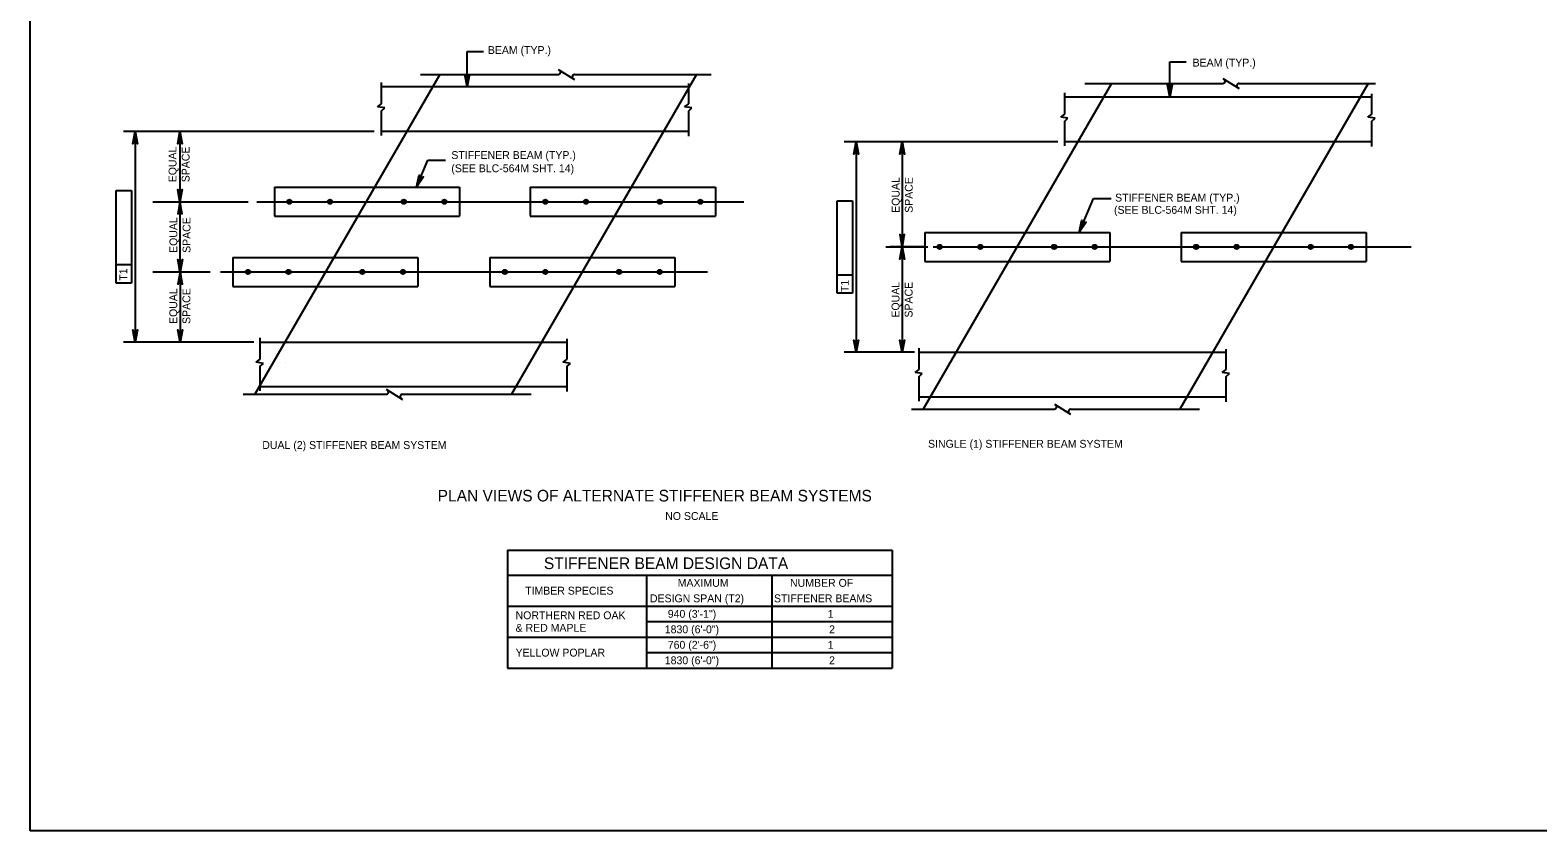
# Model space of a CAD drawing. Extents: x 638175 to 640495, y 294277 to 298435.
# Drawn here: x 639316 to 639891, y 296074 to 296380 of the extents above; entities that cross this region are included whole.
import ezdxf

# ---------------------------------------------------------------- set-up
doc = ezdxf.new("R2010")
doc.units = 0
for name, color, linetype in [('10', 7, 'Continuous'), ('2', 7, 'Continuous'), ('3', 7, 'Continuous'), ('4', 7, 'Continuous'), ('8', 7, 'Continuous')]:
    doc.layers.add(name, color=color, linetype=linetype)

msp = doc.modelspace()

# ---------------------------------------------------------------- linework, layer by layer
at = {"layer": '10'}
for p, q in [((639498.49, 296181.49), (639498.49, 296136.52)), ((639498.49, 296181.49), (639645.13, 296181.49)), ((639645.13, 296181.49), (639645.13, 296136.52)), ((639498.49, 296171.95), (639645.13, 296171.95)), ((639551.47, 296171.95), (639551.47, 296136.52)), ((639599.24, 296171.95), (639599.24, 296136.52)), ((639498.49, 296160.14), (639645.13, 296160.14)), ((639551.47, 296154.23), (639645.13, 296154.23)), ((639498.49, 296148.33), (639645.13, 296148.33)), ((639551.47, 296142.42), (639645.13, 296142.42)), ((639498.49, 296136.52), (639645.13, 296136.52))]:
    msp.add_line(p, q, dxfattribs=at)
at = {"layer": '2'}
for p, q in [((639316.46, 296074.46), (639316.46, 296638.46)), ((639472.63, 296362.87), (639402.14, 296240.92)), ((639570.46, 296362.87), (639499.97, 296240.92)), ((639728.68, 296359.46), (639656.9, 296235.27)), ((639826.52, 296359.46), (639754.73, 296235.27)), ((640102.46, 296074.46), (639316.46, 296074.46))]:
    msp.add_line(p, q, dxfattribs=at)
at = {"layer": '3'}
for p, q in [((639517.81, 296364.81), (639523.97, 296360.94)), ((639450.43, 296351.71), (639450.43, 296359.81)), ((639450.43, 296358.24), (639567.51, 296358.24)), ((639465.21, 296362.87), (639517.74, 296362.87)), ((639523.96, 296362.87), (639576.03, 296362.87)), ((639567.51, 296351.71), (639567.51, 296359.43)), ((639718.56, 296359.46), (639771.1, 296359.46)), ((639771.17, 296361.4), (639777.33, 296357.52)), ((639777.31, 296359.46), (639829.39, 296359.46)), ((639710.87, 296347.79), (639710.87, 296355.88)), ((639710.87, 296354.32), (639827.95, 296354.32)), ((639827.95, 296347.79), (639827.95, 296355.51)), ((639448.89, 296350.52), (639450.43, 296351.71)), ((639451.65, 296350.1), (639448.89, 296350.52)), ((639450.43, 296349), (639451.65, 296350.1)), ((639450.43, 296339.58), (639450.43, 296349)), ((639565.97, 296350.52), (639567.51, 296351.71)), ((639568.73, 296350.1), (639565.97, 296350.52)), ((639567.51, 296349), (639568.73, 296350.1)), ((639567.51, 296339.39), (639567.51, 296349)), ((639709.33, 296346.6), (639710.87, 296347.79)), ((639712.09, 296346.17), (639709.33, 296346.6)), ((639710.87, 296345.08), (639712.09, 296346.17)), ((639826.41, 296346.6), (639827.95, 296347.79)), ((639829.16, 296346.17), (639826.41, 296346.6)), ((639827.95, 296345.08), (639829.16, 296346.17)), ((639567.51, 296341.12), (639450.43, 296341.12)), ((639710.87, 296335.66), (639710.87, 296345.08)), ((639827.95, 296335.47), (639827.95, 296345.08)), ((639827.95, 296337.2), (639710.87, 296337.2)), ((639409.55, 296319.85), (639409.55, 296308.83)), ((639409.55, 296319.85), (639480.12, 296319.85)), ((639480.12, 296319.85), (639480.12, 296308.83)), ((639507.14, 296319.85), (639507.14, 296308.83)), ((639507.14, 296319.85), (639577.71, 296319.85)), ((639577.71, 296319.85), (639577.71, 296308.83)), ((639444.75, 296314.37), (639444.75, 296314.37)), ((639409.55, 296308.83), (639480.12, 296308.83)), ((639507.14, 296308.83), (639577.71, 296308.83)), ((639657.48, 296302.65), (639728.05, 296302.65)), ((639657.48, 296302.65), (639657.48, 296291.62)), ((639728.05, 296302.65), (639728.05, 296291.62)), ((639755.23, 296302.65), (639755.23, 296291.62)), ((639755.23, 296302.65), (639825.8, 296302.65)), ((639825.8, 296302.65), (639825.8, 296291.62)), ((639393.74, 296293.1), (639464.31, 296293.1)), ((639393.74, 296293.1), (639393.74, 296282.07)), ((639464.31, 296293.1), (639464.31, 296282.07)), ((639491.66, 296293.1), (639562.23, 296293.1)), ((639491.66, 296293.1), (639491.66, 296282.07)), ((639562.23, 296293.1), (639562.23, 296282.07)), ((639657.48, 296291.62), (639728.05, 296291.62)), ((639755.23, 296291.62), (639825.8, 296291.62)), ((639428.94, 296287.62), (639428.94, 296287.62)), ((639393.74, 296282.07), (639464.31, 296282.07)), ((639491.66, 296282.07), (639562.23, 296282.07)), ((639404.17, 296254.33), (639404.17, 296262.43)), ((639404.17, 296260.86), (639521.24, 296260.86)), ((639521.24, 296254.33), (639521.24, 296262.05)), ((639402.63, 296253.14), (639404.17, 296254.33)), ((639519.7, 296253.14), (639521.24, 296254.33)), ((639655.36, 296250.41), (639655.36, 296258.51)), ((639655.36, 296256.94), (639772.44, 296256.94)), ((639772.44, 296250.41), (639772.44, 296258.13)), ((639405.38, 296252.71), (639402.63, 296253.14)), ((639404.17, 296251.62), (639405.38, 296252.71)), ((639404.17, 296242.2), (639404.17, 296251.62)), ((639522.46, 296252.71), (639519.7, 296253.14)), ((639521.24, 296251.62), (639522.46, 296252.71)), ((639521.24, 296242.01), (639521.24, 296251.62)), ((639653.82, 296249.22), (639655.36, 296250.41)), ((639656.58, 296248.79), (639653.82, 296249.22)), ((639655.36, 296247.7), (639656.58, 296248.79)), ((639770.9, 296249.22), (639772.44, 296250.41)), ((639773.66, 296248.79), (639770.9, 296249.22)), ((639772.44, 296247.7), (639773.66, 296248.79)), ((639521.24, 296243.74), (639404.17, 296243.74)), ((639452.2, 296242.86), (639458.35, 296238.99)), ((639655.36, 296238.28), (639655.36, 296247.7)), ((639772.44, 296238.09), (639772.44, 296247.7)), ((639397.64, 296240.92), (639452.13, 296240.92)), ((639458.34, 296240.92), (639507.49, 296240.92)), ((639772.44, 296239.82), (639655.36, 296239.82)), ((639706.96, 296237.21), (639713.12, 296233.34)), ((639652.41, 296235.27), (639706.89, 296235.27)), ((639713.1, 296235.27), (639762.26, 296235.27))]:
    msp.add_line(p, q, dxfattribs=at)
for centre, radius in [((639415.31, 296314.34), 0.833), ((639415.31, 296314.34), 0.738), ((639415.31, 296314.34), 0.625), ((639415.31, 296314.34), 0.417), ((639415.31, 296314.34), 0.208), ((639430.76, 296314.34), 0.833), ((639430.76, 296314.34), 0.738), ((639430.76, 296314.34), 0.625), ((639430.76, 296314.34), 0.417), ((639430.76, 296314.34), 0.208), ((639458.91, 296314.34), 0.833), ((639458.91, 296314.34), 0.738), ((639458.91, 296314.34), 0.625), ((639458.91, 296314.34), 0.417), ((639458.91, 296314.34), 0.208), ((639474.37, 296314.34), 0.833), ((639474.37, 296314.34), 0.738), ((639474.37, 296314.34), 0.625), ((639474.37, 296314.34), 0.417), ((639474.37, 296314.34), 0.208), ((639512.9, 296314.34), 0.833), ((639512.9, 296314.34), 0.738), ((639512.9, 296314.34), 0.625), ((639512.9, 296314.34), 0.417), ((639512.9, 296314.34), 0.208), ((639528.35, 296314.34), 0.833), ((639528.35, 296314.34), 0.738), ((639528.35, 296314.34), 0.625), ((639528.35, 296314.34), 0.417), ((639528.35, 296314.34), 0.208), ((639556.5, 296314.34), 0.833), ((639556.5, 296314.34), 0.738), ((639556.5, 296314.34), 0.625), ((639556.5, 296314.34), 0.417), ((639556.5, 296314.34), 0.208), ((639571.95, 296314.34), 0.833), ((639571.95, 296314.34), 0.738), ((639571.95, 296314.34), 0.625), ((639571.95, 296314.34), 0.417), ((639571.95, 296314.34), 0.208), ((639663.23, 296297.14), 0.833), ((639663.23, 296297.14), 0.738), ((639663.23, 296297.14), 0.625), ((639663.23, 296297.14), 0.417), ((639663.23, 296297.14), 0.208), ((639678.69, 296297.14), 0.833), ((639678.69, 296297.14), 0.738), ((639678.69, 296297.14), 0.625), ((639678.69, 296297.14), 0.417), ((639678.69, 296297.14), 0.208), ((639706.84, 296297.14), 0.833), ((639706.84, 296297.14), 0.738), ((639706.84, 296297.14), 0.625), ((639706.84, 296297.14), 0.417), ((639706.84, 296297.14), 0.208), ((639722.29, 296297.14), 0.833), ((639722.29, 296297.14), 0.738), ((639722.29, 296297.14), 0.625), ((639722.29, 296297.14), 0.417), ((639722.29, 296297.14), 0.208), ((639760.98, 296297.14), 0.833), ((639760.98, 296297.14), 0.738), ((639760.98, 296297.14), 0.625), ((639760.98, 296297.14), 0.417), ((639760.98, 296297.14), 0.208), ((639776.44, 296297.14), 0.833), ((639776.44, 296297.14), 0.738), ((639776.44, 296297.14), 0.625), ((639776.44, 296297.14), 0.417), ((639776.44, 296297.14), 0.208), ((639804.59, 296297.14), 0.833), ((639804.59, 296297.14), 0.738), ((639804.59, 296297.14), 0.625), ((639804.59, 296297.14), 0.417), ((639804.59, 296297.14), 0.208), ((639820.04, 296297.14), 0.833), ((639820.04, 296297.14), 0.738), ((639820.04, 296297.14), 0.625), ((639820.04, 296297.14), 0.417), ((639820.04, 296297.14), 0.208), ((639399.5, 296287.59), 0.833), ((639399.5, 296287.59), 0.738), ((639399.5, 296287.59), 0.625), ((639399.5, 296287.59), 0.417), ((639399.5, 296287.59), 0.208), ((639414.95, 296287.59), 0.833), ((639414.95, 296287.59), 0.738), ((639414.95, 296287.59), 0.625), ((639414.95, 296287.59), 0.417), ((639414.95, 296287.59), 0.208), ((639443.1, 296287.59), 0.833), ((639443.1, 296287.59), 0.738), ((639443.1, 296287.59), 0.625), ((639443.1, 296287.59), 0.417), ((639443.1, 296287.59), 0.208), ((639458.56, 296287.59), 0.833), ((639458.56, 296287.59), 0.738), ((639458.56, 296287.59), 0.625), ((639458.56, 296287.59), 0.417), ((639458.56, 296287.59), 0.208), ((639497.42, 296287.59), 0.833), ((639497.42, 296287.59), 0.738), ((639497.42, 296287.59), 0.625), ((639497.42, 296287.59), 0.417), ((639497.42, 296287.59), 0.208), ((639512.87, 296287.59), 0.833), ((639512.87, 296287.59), 0.738), ((639512.87, 296287.59), 0.625), ((639512.87, 296287.59), 0.417), ((639512.87, 296287.59), 0.208), ((639541.02, 296287.59), 0.833), ((639541.02, 296287.59), 0.738), ((639541.02, 296287.59), 0.625), ((639541.02, 296287.59), 0.417), ((639541.02, 296287.59), 0.208), ((639556.47, 296287.59), 0.833), ((639556.47, 296287.59), 0.738), ((639556.47, 296287.59), 0.625), ((639556.47, 296287.59), 0.417), ((639556.47, 296287.59), 0.208)]:
    msp.add_circle(centre, radius, dxfattribs=at)
for centre, start, end in [((639517.74, 296363.78), 270, 60), ((639524.04, 296361.97), 95.32859, 237.86724), ((639771.1, 296360.37), 270, 60), ((639777.4, 296358.55), 95.32859, 237.86724), ((639452.13, 296241.83), 270, 60), ((639458.43, 296240.02), 95.32859, 237.86724), ((639706.89, 296236.18), 270, 60), ((639713.19, 296234.37), 95.32859, 237.86724)]:
    msp.add_arc(centre, 0.909, start, end, dxfattribs=at)
at = {"layer": '4'}
for p, q in [((639483.02, 296371.58), (639489.27, 296371.58)), ((639750.97, 296367.66), (639757.19, 296367.66)), ((639390.24, 296341.12), (639352, 296341.12)), ((639356.5, 296341.12), (639356.5, 296260.86)), ((639447.62, 296341.12), (639362.44, 296341.12)), ((639386.42, 296341.12), (639371.37, 296341.12)), ((639373.58, 296341.12), (639373.58, 296314.37)), ((639657.84, 296337.2), (639626.84, 296337.2)), ((639631.34, 296337.2), (639631.34, 296256.94)), ((639708.28, 296337.2), (639644.35, 296337.2)), ((639648.85, 296337.2), (639648.85, 296297.17)), ((639468.1, 296330.16), (639474.77, 296330.16)), ((639349.21, 296318.66), (639355.12, 296318.66)), ((639349.21, 296283.36), (639349.21, 296318.66)), ((639355.12, 296318.66), (639355.12, 296283.36)), ((639363.28, 296314.37), (639399.58, 296314.37)), ((639373.58, 296314.37), (639373.58, 296290.57)), ((639402.9, 296314.37), (639588.55, 296314.37)), ((639624.06, 296314.74), (639629.96, 296314.74)), ((639624.06, 296286.91), (639624.06, 296314.74)), ((639629.96, 296314.74), (639629.96, 296279.44)), ((639721.86, 296315.62), (639728.56, 296315.62)), ((639642.73, 296297.17), (639658.72, 296297.17)), ((639657.84, 296297.17), (639644.35, 296297.17)), ((639648.85, 296297.17), (639648.85, 296256.94)), ((639660.68, 296297.14), (639842.96, 296297.14)), ((639355.12, 296290.25), (639349.21, 296290.25)), ((639355.12, 296283.36), (639349.21, 296283.36)), ((639363.28, 296287.62), (639385.08, 296287.62)), ((639373.64, 296284.66), (639373.64, 296260.86)), ((639389.04, 296287.58), (639574.69, 296287.58)), ((639624.06, 296279.44), (639624.06, 296286.91)), ((639629.96, 296286.33), (639624.06, 296286.33)), ((639629.96, 296279.44), (639624.06, 296279.44)), ((639401.7, 296260.86), (639352, 296260.86)), ((639380.13, 296260.86), (639371.75, 296260.86)), ((639653.54, 296256.94), (639626.84, 296256.94))]:
    msp.add_line(p, q, dxfattribs=at)
for points in [[(639483.02, 296358.24), (639483.02, 296371.58)], [(639750.97, 296354.32), (639750.97, 296367.66)], [(639483.02, 296358.24), (639482.15, 296362.9), (639482.39, 296362.55), (639482.71, 296362.36), (639483.02, 296362.31), (639483.33, 296362.36), (639483.64, 296362.55), (639483.89, 296362.9), (639483.02, 296358.24), (639483.64, 296362.55), (639483.33, 296362.36), (639483.02, 296358.24), (639483.02, 296362.31), (639482.71, 296362.36), (639483.02, 296358.24), (639482.39, 296362.55)], [(639750.97, 296354.32), (639750.1, 296358.98), (639750.35, 296358.62), (639750.66, 296358.44), (639750.97, 296358.38), (639751.28, 296358.44), (639751.6, 296358.62), (639751.85, 296358.98), (639750.97, 296354.32), (639751.6, 296358.62), (639751.28, 296358.44), (639750.97, 296354.32), (639750.97, 296358.38), (639750.66, 296358.44), (639750.97, 296354.32), (639750.35, 296358.62)], [(639356.5, 296341.12), (639357.37, 296336.46), (639357.13, 296336.82), (639356.81, 296337), (639356.5, 296337.06), (639356.19, 296337), (639355.88, 296336.82), (639355.63, 296336.46), (639356.5, 296341.12), (639355.88, 296336.82), (639356.19, 296337), (639356.5, 296341.12), (639356.5, 296337.06), (639356.81, 296337), (639356.5, 296341.12), (639357.13, 296336.82)], [(639373.58, 296341.12), (639374.45, 296336.46), (639374.2, 296336.82), (639373.89, 296337), (639373.58, 296337.06), (639373.27, 296337), (639372.95, 296336.82), (639372.71, 296336.46), (639373.58, 296341.12), (639372.95, 296336.82), (639373.27, 296337), (639373.58, 296341.12), (639373.58, 296337.06), (639373.89, 296337), (639373.58, 296341.12), (639374.2, 296336.82)], [(639631.34, 296337.2), (639632.22, 296332.54), (639631.97, 296332.9), (639631.66, 296333.08), (639631.34, 296333.14), (639631.03, 296333.08), (639630.72, 296332.9), (639630.47, 296332.54), (639631.34, 296337.2), (639630.72, 296332.9), (639631.03, 296333.08), (639631.34, 296337.2), (639631.34, 296333.14), (639631.66, 296333.08), (639631.34, 296337.2), (639631.97, 296332.9)], [(639648.85, 296337.2), (639649.73, 296332.54), (639649.48, 296332.9), (639649.17, 296333.08), (639648.85, 296333.14), (639648.54, 296333.08), (639648.23, 296332.9), (639647.98, 296332.54), (639648.85, 296337.2), (639648.23, 296332.9), (639648.54, 296333.08), (639648.85, 296337.2), (639648.85, 296333.14), (639649.17, 296333.08), (639648.85, 296337.2), (639649.48, 296332.9)], [(639463.79, 296319.85), (639468.1, 296330.16)], [(639463.79, 296319.85), (639464.78, 296324.48), (639464.87, 296324.06), (639465.09, 296323.77), (639465.36, 296323.6), (639465.67, 296323.53), (639466.03, 296323.58), (639466.39, 296323.81), (639463.79, 296319.85), (639466.03, 296323.58), (639465.67, 296323.53), (639463.79, 296319.85), (639465.36, 296323.6), (639465.09, 296323.77), (639463.79, 296319.85), (639464.87, 296324.06)], [(639373.58, 296314.37), (639372.71, 296319.03), (639372.95, 296318.67), (639373.27, 296318.48), (639373.58, 296318.43), (639373.89, 296318.48), (639374.2, 296318.67), (639374.45, 296319.03), (639373.58, 296314.37), (639374.2, 296318.67), (639373.89, 296318.48), (639373.58, 296314.37), (639373.58, 296318.43), (639373.27, 296318.48), (639373.58, 296314.37), (639372.95, 296318.67)], [(639373.58, 296314.37), (639372.71, 296309.71), (639372.95, 296310.07), (639373.27, 296310.25), (639373.58, 296310.31), (639373.89, 296310.25), (639374.2, 296310.07), (639374.45, 296309.71), (639373.58, 296314.37), (639374.2, 296310.07), (639373.89, 296310.25), (639373.58, 296314.37), (639373.58, 296310.31), (639373.27, 296310.25), (639373.58, 296314.37), (639372.95, 296310.07)], [(639716.43, 296302.65), (639721.87, 296315.62)], [(639716.43, 296302.65), (639717.43, 296307.28), (639717.52, 296306.86), (639717.73, 296306.57), (639718, 296306.39), (639718.31, 296306.32), (639718.67, 296306.37), (639719.04, 296306.61), (639716.43, 296302.65), (639718.67, 296306.37), (639718.31, 296306.32), (639716.43, 296302.65), (639718, 296306.39), (639717.73, 296306.57), (639716.43, 296302.65), (639717.52, 296306.86)], [(639648.85, 296297.17), (639649.73, 296301.83), (639649.48, 296301.47), (639649.17, 296301.28), (639648.85, 296301.23), (639648.54, 296301.28), (639648.23, 296301.47), (639647.98, 296301.83), (639648.85, 296297.17), (639648.23, 296301.47), (639648.54, 296301.28), (639648.85, 296297.17), (639648.85, 296301.23), (639649.17, 296301.28), (639648.85, 296297.17), (639649.48, 296301.47)], [(639648.85, 296297.17), (639649.73, 296292.51), (639649.48, 296292.86), (639649.17, 296293.05), (639648.85, 296293.1), (639648.54, 296293.05), (639648.23, 296292.86), (639647.98, 296292.51), (639648.85, 296297.17), (639648.23, 296292.86), (639648.54, 296293.05), (639648.85, 296297.17), (639648.85, 296293.1), (639649.17, 296293.05), (639648.85, 296297.17), (639649.48, 296292.86)], [(639373.64, 296287.62), (639372.77, 296292.28), (639373.02, 296291.92), (639373.33, 296291.73), (639373.64, 296291.68), (639373.95, 296291.73), (639374.27, 296291.92), (639374.52, 296292.28), (639373.64, 296287.62), (639374.27, 296291.92), (639373.95, 296291.73), (639373.64, 296287.62), (639373.64, 296291.68), (639373.33, 296291.73), (639373.64, 296287.62), (639373.02, 296291.92)], [(639373.64, 296287.62), (639372.77, 296282.96), (639373.02, 296283.31), (639373.33, 296283.5), (639373.64, 296283.55), (639373.95, 296283.5), (639374.27, 296283.31), (639374.52, 296282.96), (639373.64, 296287.62), (639374.27, 296283.31), (639373.95, 296283.5), (639373.64, 296287.62), (639373.64, 296283.55), (639373.33, 296283.5), (639373.64, 296287.62), (639373.02, 296283.31)], [(639356.5, 296260.86), (639355.63, 296265.52), (639355.88, 296265.17), (639356.19, 296264.98), (639356.5, 296264.93), (639356.81, 296264.98), (639357.13, 296265.17), (639357.37, 296265.52), (639356.5, 296260.86), (639357.13, 296265.17), (639356.81, 296264.98), (639356.5, 296260.86), (639356.5, 296264.93), (639356.19, 296264.98), (639356.5, 296260.86), (639355.88, 296265.17)], [(639373.64, 296260.86), (639372.77, 296265.52), (639373.02, 296265.17), (639373.33, 296264.98), (639373.64, 296264.93), (639373.95, 296264.98), (639374.27, 296265.17), (639374.52, 296265.52), (639373.64, 296260.86), (639374.27, 296265.17), (639373.95, 296264.98), (639373.64, 296260.86), (639373.64, 296264.93), (639373.33, 296264.98), (639373.64, 296260.86), (639373.02, 296265.17)], [(639631.34, 296256.94), (639630.47, 296261.6), (639630.72, 296261.24), (639631.03, 296261.06), (639631.34, 296261.01), (639631.66, 296261.06), (639631.97, 296261.24), (639632.22, 296261.6), (639631.34, 296256.94), (639631.97, 296261.24), (639631.66, 296261.06), (639631.34, 296256.94), (639631.34, 296261.01), (639631.03, 296261.06), (639631.34, 296256.94), (639630.72, 296261.24)], [(639648.85, 296256.94), (639647.98, 296261.6), (639648.23, 296261.24), (639648.54, 296261.06), (639648.85, 296261.01), (639649.17, 296261.06), (639649.48, 296261.24), (639649.73, 296261.6), (639648.85, 296256.94), (639649.48, 296261.24), (639649.17, 296261.06), (639648.85, 296256.94), (639648.85, 296261.01), (639648.54, 296261.06), (639648.85, 296256.94), (639648.23, 296261.24)]]:
    msp.add_lwpolyline(points, dxfattribs=at)
for points in [[(639483.02, 296358.24), (639483.05, 296358.36), (639482.99, 296358.36)], [(639750.97, 296354.32), (639751, 296354.44), (639750.94, 296354.44)], [(639630.84, 296334.2), (639631.84, 296334.2), (639631.34, 296337.2)], [(639648.35, 296334.2), (639649.35, 296334.2), (639648.85, 296337.2)], [(639463.79, 296319.85), (639463.86, 296319.95), (639463.8, 296319.97)], [(639648.35, 296300.17), (639649.35, 296300.17), (639648.85, 296297.17)], [(639716.43, 296302.65), (639716.51, 296302.75), (639716.45, 296302.77)], [(639648.35, 296294.17), (639649.35, 296294.17), (639648.85, 296297.17)], [(639373.09, 296290.57), (639374.07, 296290.57), (639373.58, 296287.62)], [(639373.15, 296284.66), (639374.13, 296284.66), (639373.64, 296287.62)], [(639356, 296263.86), (639357, 296263.86), (639356.5, 296260.86)], [(639373.15, 296263.82), (639374.13, 296263.82), (639373.64, 296260.86)], [(639630.84, 296259.94), (639631.84, 296259.94), (639631.34, 296256.94)], [(639648.35, 296260.13), (639649.35, 296260.13), (639648.85, 296257.13)]]:
    msp.add_lwpolyline(points, close=True, dxfattribs=at)
at = {"layer": '8'}
for p, q in [((639460.71, 296350.35), (639460.71, 296350.35)), ((639460.73, 296350.38), (639460.73, 296350.38)), ((639444.75, 296314.37), (639444.75, 296314.37)), ((639428.94, 296287.62), (639428.94, 296287.62)), ((639413.66, 296252.97), (639413.66, 296252.97))]:
    msp.add_line(p, q, dxfattribs=at)

# ---------------------------------------------------------------- texts
at = {"layer": '4'}
for s, height, p in [('BEAM (TYP.)', 3, (639490.94, 296370.68)), ('BEAM (TYP.)', 3, (639759.62, 296365.9)), ('STIFFENER BEAM (TYP.)', 3, (639477.02, 296330.65)), ('(SEE BLC-564M SHT. 14)', 3, (639477.02, 296325.6)), ('STIFFENER BEAM (TYP.)', 3, (639730.08, 296314.4)), ('(SEE BLC-564M SHT. 14)', 3, (639729.67, 296309.75)), ('DUAL (2) STIFFENER BEAM SYSTEM', 3, (639404.96, 296220.08)), ('SINGLE (1) STIFFENER BEAM SYSTEM', 3, (639658.76, 296220.54)), ('PLAN VIEWS OF ALTERNATE STIFFENER BEAM SYSTEMS', 4.4292, (639471.81, 296200.06)), ('NO SCALE', 3, (639558.56, 296193.01)), ('STIFFENER BEAM DESIGN DATA', 4.4292, (639512.31, 296174.28)), ('MAXIMUM', 3, (639563.33, 296167.52)), ('NUMBER OF ', 3, (639606.16, 296167.52)), ('TIMBER SPECIES', 3, (639505.16, 296164.54)), ('DESIGN SPAN (T2)', 3, (639552.74, 296161.61)), ('STIFFENER BEAMS', 3, (639600.03, 296161.61)), ('NORTHERN RED OAK', 3, (639501.52, 296155.16)), ('940 (3\'-1")', 3, (639559.54, 296155.71)), ('1', 3, (639620.52, 296155.71)), ('& RED MAPLE', 3, (639501.52, 296150.38)), ('1830 (6\'-0")', 3, (639558.4, 296149.8)), ('2', 3, (639621.04, 296149.8)), ('760 (2\'-6")', 3, (639559.54, 296143.9)), ('1', 3, (639620.52, 296143.9)), ('YELLOW POPLAR', 3, (639501.52, 296140.92)), ('1830 (6\'-0")', 3, (639558.4, 296137.99)), ('2', 3, (639621.04, 296137.99))]:
    msp.add_text(s, height=height, dxfattribs=at).set_placement(p)
for p in [(639353.47, 296284.24), (639628.53, 296279.87)]:
    msp.add_text('T1', height=3, rotation=90, dxfattribs=at).set_placement(p)
at = {"layer": '8'}
for s, p in [('EQUAL ', (639372.23, 296321.78)), ('SPACE', (639377.23, 296321.78)), ('EQUAL ', (639647.92, 296310.12)), ('SPACE', (639652.92, 296310.12)), ('EQUAL ', (639372.57, 296294.84)), ('SPACE', (639377.57, 296294.84)), ('EQUAL ', (639647.86, 296270.19)), ('SPACE', (639652.86, 296270.19)), ('EQUAL ', (639372.53, 296267.74)), ('SPACE', (639377.53, 296267.74))]:
    msp.add_text(s, height=3, rotation=89.9708, dxfattribs=at).set_placement(p)

doc.saveas('drawing.dxf')
